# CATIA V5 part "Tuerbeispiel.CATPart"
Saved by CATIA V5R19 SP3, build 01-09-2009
Part number: Part1
Bounding box of the stored display mesh (mm): x 0 to 56.103, y -34 to 75.67, z -22.402 to 22.357
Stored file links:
  C:\Dokumente und Einstellungen\frauendan\Desktop\Tuerbeispiel.CATPart
  C:\Dokumente und Einstellungen\frauendan\Desktop\Steuertabelle.xls
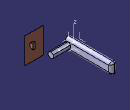
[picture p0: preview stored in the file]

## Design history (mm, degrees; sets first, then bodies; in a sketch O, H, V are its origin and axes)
Parameters
  Tuerstatus = "Geschlossen" {design table}
AxisSystem1: origin (0, 0, 0), X (1, 0, 0), Y (0, 1, 0), Z (0, 0, 1)
Set1
  Plane1: type Offset, RefPlane ZX plane of AxisSystem1, Offset -29
  Fill1: Boundary Sketch1
  Sketch1 on Plane1, origin (0, -29, 0), H (-1, 0, 0), V (0, 0, 1)
    line L1 (-56.1025, 22.3574) -> (-24.325, 22.3574)
    line L2 (-24.325, 22.3574) -> (-24.325, -22.4017)
    line L3 (-24.325, -22.4017) -> (-56.1025, -22.4017)
    line L4 (-56.1025, -22.4017) -> (-56.1025, 22.3574)
    horizontal: L1 H, L3 H
    vertical: L2 V, L4 V
Body1 "Griff (Rotate)" (main body)
  Sketch2 on YZ plane of AxisSystem1, origin (0, 0, 0), H (0, 1, 0), V (0, 0, 1)
    point P1 (0, 0)
    point P2 (4.3301, -2.5)
    point P3 (4.3301, 2.5)
    point P4 (0, 5)
    point P5 (-4.3301, 2.5)
    point P6 (-4.3301, -2.5)
    point P7 (0, -5)
    point P8 (4.3301, 0)
    line L1 (4.3301, -2.5) -> (4.3301, 2.5)
    line L2 (4.3301, 2.5) -> (0, 5)
    line L3 (0, 5) -> (-4.3301, 2.5)
    line L4 (-4.3301, 2.5) -> (-4.3301, -2.5)
    line L5 (-4.3301, -2.5) -> (0, -5)
    line L6 (0, -5) -> (4.3301, -2.5)
    construction line L7 (0, 0) -> (4.3301, 0)
    construction circle A1 centre (0, 0) radius 5
    construction arc A2 centre (-4.3301, -2.5) radius 5 from (-4.3301, 2.5) to (0, -5) cw
    construction arc A3 centre (4.3301, 2.5) radius 5 from (0, 5) to (4.3301, -2.5) ccw
    radius A1 = 5
    horizontal: L7 H
    coincidence: A1 P2, A1 P3, A1 P4, A1 P5, A1 P6, A1 P7, A2 P1, A3 P1, P1 O
    midpoint: P8 L1
    parallelism: L1 L4
  Pad1: profile Sketch2, direction (1, 0, 0), length 40
  Sketch3 on start face of Pad1, origin (0, 0, 0), H (0, -1, 0), V (0, 0, 1)
    line L1 (-72.6699, 10) -> (4.3301, 10)
    line L2 (4.3301, 10) -> (4.3301, -10)
    line L3 (4.3301, -10) -> (-72.6699, -10)
    line L4 (-75.6699, -7) -> (-75.6699, 7)
    point P2 (4.3301, -10)
    point P3 (-75.6699, -10)
    reference projected line E1 (4.3301, 2.5) -> (4.3301, -2.5) from edge [start face of Pad1 | face of Pad1 from Sketch2.L4]
    arc A1 centre (-72.6699, 7) radius 3 from (-72.6699, 10) to (-75.6699, 7) ccw
    arc A2 centre (-72.6699, -7) radius 3 from (-72.6699, -10) to (-75.6699, -7) cw
    reference projected point E2 (0, 5) from vertex [face of Pad1 from Sketch2.L3 | start face of Pad1 | face of Pad1 from Sketch2.L2]
    reference projected point E3 (0, -5) from vertex [face of Pad1 from Sketch2.L6 | start face of Pad1 | face of Pad1 from Sketch2.L5]
    radius A1 = 3
    distance P2 P3 = 80
    radius A2 = 3
    distance L1 E2 = 5
    distance E3 L3 = 5
    horizontal: L1 H, L3 H
    vertical: L2 V, L4 V
    coincidence: E1 L2, L3 P3, L4 P3
    tangency: A1 L1, A1 L4, A2 L3, A2 L4
  Pad2: profile Sketch3, direction (1, 0, 0), length 10
  Fillet1: radius 5, on edge [end face of Pad2 | face of Pad2 from Sketch3.L1]; edge [face of Pad2 from Sketch3.L1 | face of Pad2]
  Rotate1 "Rotation_Griff": ToTransfor Fillet1, Angle 345, Axis edge [XY plane of AxisSystem1 | ZX plane of AxisSystem1]
Body2 "Nase (Translate)"
  Sketch4 on end face of Pad1, origin (40, 0, 0), H (0, 1, 0), V (0, 0, 1)
    line L1 (-29, 4.798) -> (-34, 2.0595)
    line L2 (-34, 2.0595) -> (-34, -3.7007)
    line L3 (-34, -3.7007) -> (-29, -5.8726)
    line L4 (-29, -5.8726) -> (-29, 4.798)
    reference intersected line E1 (-29, -22.4017) -> (-29, 22.3574) from Fill1
    distance L2 L4 = 5
    vertical: L2 V, L4 V
    coincidence: L4 E1
  Pad3: profile Sketch4, direction (1, 0, 0), length 2, mirrored extent
  Translate1 "Translation_Nase": Direction edge [YZ plane of AxisSystem1 | XY plane of AxisSystem1], ToTransfor Pad3, Length 5
Relations
  design table "Steuertabelle", configuration 2, drives Tuerstatus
